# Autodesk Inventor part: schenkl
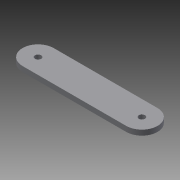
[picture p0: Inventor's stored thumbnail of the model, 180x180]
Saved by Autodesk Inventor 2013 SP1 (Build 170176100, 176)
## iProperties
Created: 2012-11
Part Number: schenkl
Material: Allgemein
Document SubType Name: Modeling
Designer: macuser
Density: 1 g/cm^3
Author: macuser
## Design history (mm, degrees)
sketch "Skizze1"
  geometry: L1 (0, -42)-(0, 42) reference; L2 (-82, 0)-(282, 0) reference; L3 (0, 30)-(200, 30); L4 (0, -30)-(200, -30); C1 r 6 at (0, 0); C2 r 6 at (200, 0); A1 r 30 centre (0, 0) between (0, 30) and (0, -30); A2 r 30 centre (200, 0) between (200, 30) and (200, -30); 1 further point
  constraints: 4 centre point, 4 end point, 4 point on circle, 2 coincident, 2 parallel, 2 point on line, 2 tangent
  dimensions: "d0" = 60 diameter of A1; "d1" = 60 diameter of A2; "d2" = 0 distance from line of L1 A1.centre; "d3" = 200 distance of A2.centre point (0, 0); "d4" = 12 diameter of C1; "d5" = 12 diameter of C2
extrude "Extrusion1" new body sketch "Skizze1" distance "d6" = 10; taper "d7" = 0 deg
node "Volumenkörper1"
